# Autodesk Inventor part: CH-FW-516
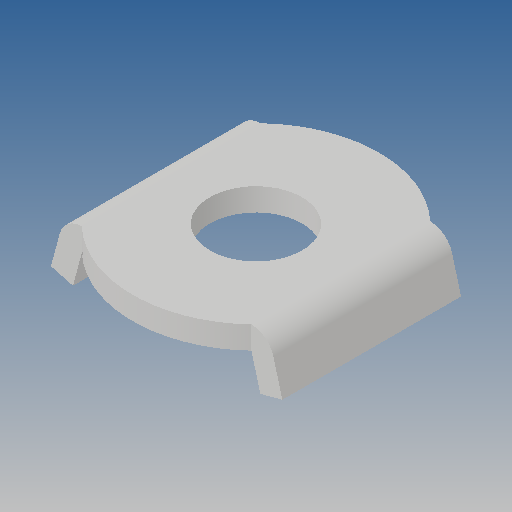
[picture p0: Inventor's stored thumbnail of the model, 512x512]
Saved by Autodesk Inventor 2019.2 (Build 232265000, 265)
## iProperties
Created: 2012-09
Part Number: CH-FW-516
Material: Ogólny
Document SubType Name: Modeling
Designer: CADENGINEERING4
Density: 1 g/cm^3
Appearance: Domyślna
Author: CADENGINEERING4
Revision Number: ÈÎºÎ
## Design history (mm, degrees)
feature "ÇÐ³ý-À­Éì4"
node "Bryła1"
